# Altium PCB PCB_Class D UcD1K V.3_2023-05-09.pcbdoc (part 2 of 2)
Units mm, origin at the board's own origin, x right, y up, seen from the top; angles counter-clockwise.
Board outline 217.55 x 90.42 mm, 2 copper layers (Top Layer, Bottom Layer); 170 components, 120 nets, 574 pads, 13 vias.
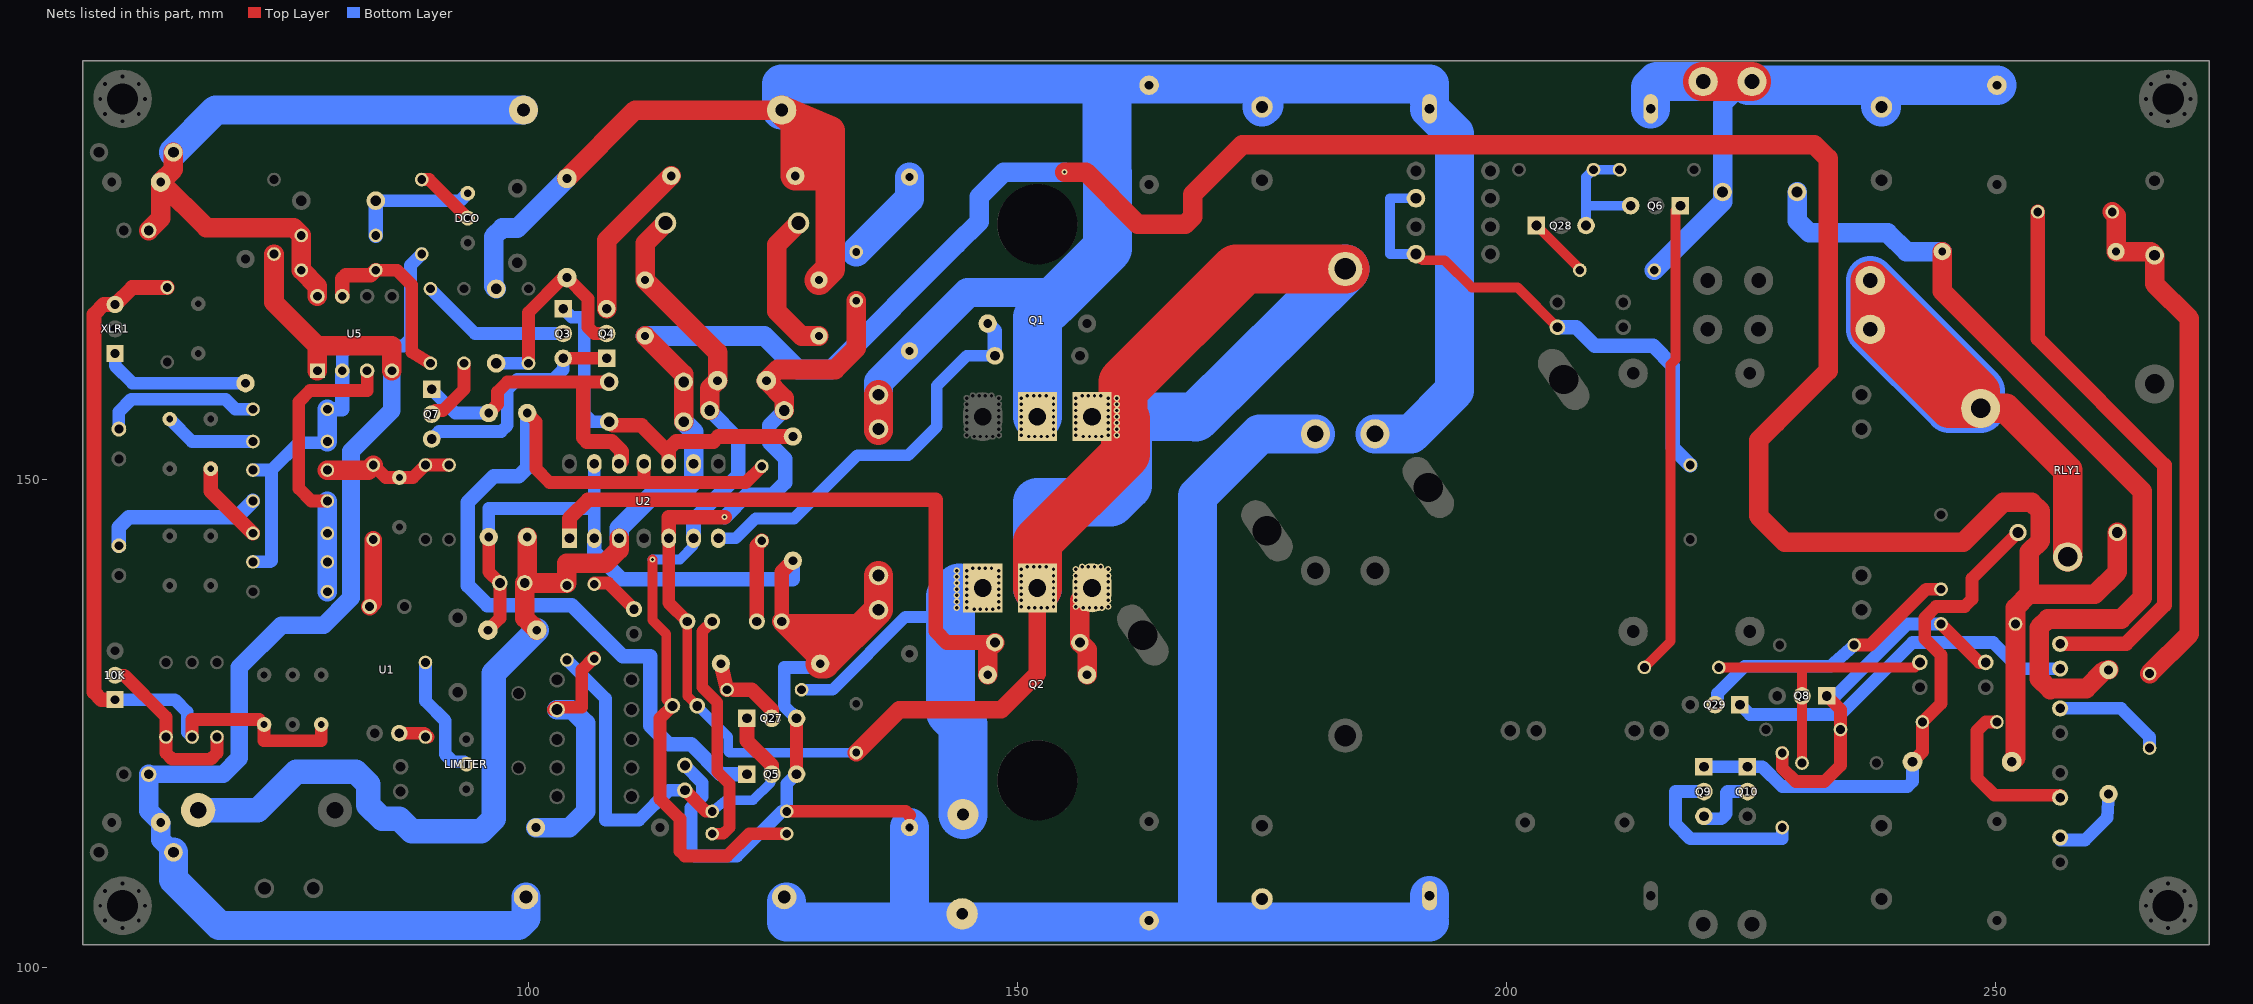
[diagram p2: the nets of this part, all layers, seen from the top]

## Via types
v1: diameter 0.61, hole 0.305, Top Layer to Bottom Layer, tented both sides, 13 vias

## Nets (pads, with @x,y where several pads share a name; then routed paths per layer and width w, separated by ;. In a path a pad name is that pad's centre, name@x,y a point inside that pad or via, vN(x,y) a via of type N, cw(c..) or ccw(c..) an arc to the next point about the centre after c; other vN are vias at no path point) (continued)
Q1_2: C1.2 C4.2 C44.1 C45.2 D8.2 D22.1 pad.2@135.763,155.111 pad.8@150.368,154.476 pad.8@150.368,155.111 pad.8@150.368,155.746 pad.8@150.368,156.381 pad.8@150.368,157.016 pad.8@150.368,157.651 pad.8@150.368,158.286 pad.8@151.003,158.54 pad.8@151.13,154.349 pad.8@151.638,158.54 pad.8@151.765,154.349 pad.8@152.4,154.349 pad.8@152.273,158.54 pad.8@152.908,158.54 pad.8@153.035,154.349 pad.8@153.67,154.476 pad.8@153.67,155.111 pad.8@153.67,155.746 pad.8@153.67,156.381 pad.8@153.67,157.016 pad.8@153.67,157.651 pad.8@153.67,158.286 Q1.2 R4.1 R7.1 R43.2 R78.1 U10.2 | length 269.2
  Top Layer w2: C4.2@103.886,180.765 110.871,187.75 R78.1@125.857,187.75 127.254,186.353 R4.1@127.254,181.019
  Top Layer w3: 128.016,185.591 128.016,181.781 R4.1@127.254,181.019 ; R7.1@129.667,170.351 130.81,171.494 130.81,181.019 ; 129.917,185.591 129.917,181.913 130.81,181.019 ; pad.2@135.763,154.984 135.763,156.716 C1.2@135.763,158.618 ; R4.1@127.254,181.019 127.254,186.353 R78.1@125.857,187.75 130.81,185.65 130.81,181.019 ; R4.1@127.254,181.019 130.81,181.019
  Bottom Layer w2: D8.2@96.647,169.462 96.393,169.716 96.393,174.796 97.282,175.685 98.806,175.685 C4.2@103.886,180.765
  Bottom Layer w3: pad.2@135.763,155.111 C1.2@135.763,158.618 135.763,159.937 R43.2@138.938,163.112 144.907,169.081 153.924,169.081
  Bottom Layer w4: R78.1@125.857,187.75 125.867,190.417 192.151,190.417 U10.2@192.151,188.512 ; C44.1@175.006,188.071 175.182,188.248 175.182,190.29 ; D22.1@186.563,154.618 190.261,154.618 194.691,159.048 194.691,185.327 U10.2@192.141,187.877
  Bottom Layer w5: Q1.2@152.019,156.381 152.019,166.541 153.924,168.319 159.191,173.586 159.131,189.782
Q2_1: D4.1 pad.8@155.956,136.95 pad.8@155.956,137.585 pad.8@155.956,138.22 pad.8@155.956,138.855 pad.8@155.956,139.49 pad.8@155.956,140.76 pad.8@155.956,140.125 pad.8@156.591,141.014 pad.8@156.718,136.823 pad.8@157.226,141.014 pad.8@157.353,136.823 pad.8@157.861,141.014 pad.8@157.988,136.823 pad.8@158.496,141.014 pad.8@158.623,136.823 pad.8@159.258,136.95 pad.8@159.258,137.585 pad.8@159.258,138.22 pad.8@159.258,138.855 pad.8@159.258,139.49 pad.8@159.258,140.76 pad.8@159.258,140.125 Q2.1 R1.2 | length 9.7
  Top Layer w2: R1.2@157.099,129.965 157.099,132.537 D4.1@156.369,133.267 156.369,137.617 Q2.1@157.607,138.855
Q2_3: pad.8@143.764,136.823 pad.8@143.764,137.458 pad.8@143.764,138.093 pad.8@143.764,138.728 pad.8@143.764,139.363 pad.8@143.764,139.998 pad.8@143.764,140.633 pad.8@144.78,136.823 pad.8@144.78,137.458 pad.8@144.78,138.093 pad.8@144.78,138.728 pad.8@144.78,139.363 pad.8@144.78,139.998 pad.8@144.78,140.633 pad.8@145.415,140.887 pad.8@145.542,136.696 pad.8@146.05,140.887 pad.8@146.177,136.696 pad.8@146.685,140.887 pad.8@146.812,136.696 pad.8@147.32,140.887 pad.8@147.447,136.696 pad.8@148.082,136.823 pad.8@148.082,137.458 pad.8@148.082,138.093 pad.8@148.082,138.728 pad.8@148.082,139.363 pad.8@148.082,139.998 pad.8@148.082,140.633 pad.9@145.542,138.855 Q2.3 R30.1 R40.1 | length 41.8
  Bottom Layer w1.2: R30.1@128.524,128.441 131.064,128.441 138.517,135.894 143.129,135.894
  Bottom Layer w5: pad.8@144.018,138.855 143.129,137.966 143.129,126.155 144.399,124.885 R40.1@144.399,115.684
Q3_2: Q3.2 R6.2 | length 15.5
  Bottom Layer w1.3: R6.2@89.916,169.462 94.488,164.89 Q3.2@103.505,164.89
Q4_2: C4.1 D8.1 Q4.2 R5.1 | length 22.1
  Top Layer w1.3: R5.1@99.949,161.842 99.949,167.049 103.505,170.605 C4.1@103.886,170.605 106.045,168.446 106.045,165.525 106.68,164.89 Q4.2@107.95,164.89
  Bottom Layer w1.3: D8.1@96.647,161.842 R5.1@99.949,161.842
Q4_3: Q4.3 R4.2 | length 16.3
  Top Layer w2: Q4.3@107.95,167.43 107.95,174.415 R4.2@114.554,181.019
Q6_1: Q6.1 R50.1 | length 48.8
  Top Layer w1: R50.1@214.122,130.727 216.789,133.394 216.789,161.715 217.297,162.223 217.297,177.463 Q6.1@217.805,177.971
Q7_2: Q7.2 R2.1 | length 7
  Top Layer w1.3: Q7.2@90.043,156.635 90.424,157.016 91.186,157.016 93.345,159.175 R2.1@93.345,161.842
Q7_3: Q3.3 Q4.1 Q7.3 | length 24.2
  Top Layer w1.3: Q3.3@103.505,162.35 Q4.1@107.95,162.35
  Bottom Layer w1.3: Q7.3@90.043,154.095 90.805,154.857 97.155,154.857 97.79,155.492 97.79,159.175 98.806,160.191 102.489,160.191 103.505,161.207 Q3.3@103.505,162.35
Q8_1: C29.1 Q8.1 R52.1 R54.2 R55.1 | length 37.4
  Top Layer w1.3: R55.1@228.219,121.964 228.219,120.44 229.616,119.043 232.537,119.043 234.188,120.694 R52.1@234.188,124.377 234.188,126.409 Q8.1@232.791,127.806 ; R54.2@244.475,135.172 248.412,131.235 C29.1@249.047,131.235
  Bottom Layer w1.3: Q8.1@232.791,127.806 233.68,127.806 241.046,135.172 R54.2@244.475,135.172
Q8_2: C26.1 Q8.2 R50.2 R51.1 | length 32
  Top Layer w1: R50.2@221.742,130.727 230.251,130.727 Q8.2@230.251,127.806 R51.1@230.251,120.948 ; 228.854,130.727 241.808,130.727 C26.1@242.316,131.235
Q9_1: D24.1 Q9.1 Q10.1 R56.1 RLY1.4 | length 55.4
  Top Layer w1.3: D24.1@241.554,121.075 242.57,122.091 R56.1@242.57,125.139 244.475,127.044 244.475,131.997 242.824,133.648 242.824,135.807 243.967,136.95 246.888,136.95 247.65,137.712 247.65,139.831 RLY1.4@252.349,144.53
  Bottom Layer w1.3: Q9.1@220.218,120.567 220.472,120.567 Q10.1@224.663,120.567 226.187,120.567 228.219,118.535 241.046,118.535 241.554,119.043 D24.1@241.554,121.075
Q9_3: Q9.3 Q10.2 | length 6.9
  Bottom Layer w1.3: Q9.3@220.218,115.233 221.996,115.233 222.504,115.741 222.504,117.9 222.631,118.027 Q10.2@224.663,118.027
Q27_1: C16.1 Q5.2 Q27.1 R31.1 R32.2 | length 45.6
  Top Layer w1.3: C16.1@115.951,118.154 118.11,115.995 R32.2@118.745,115.995
  Top Layer w1.5: Q27.1@122.301,125.52 122.301,123.869 122.301,123.234 124.841,120.694 Q5.2@124.841,119.805
  Bottom Layer w1: R32.2@118.745,115.995 120.142,117.138 122.936,117.138 124.714,118.917 Q5.2@124.714,119.551
  Bottom Layer w1.3: R31.1@103.886,131.489 107.823,127.552 107.823,115.106 111.252,115.106 114.3,118.154 C16.1@115.951,118.154
Q28_1: Q28.1 R49.2 | length 6.4
  Top Layer w1: Q28.1@203.073,175.939 207.518,171.494 R49.2@207.518,171.367
Q29_1: Q29.1 R60.2 | length 37.3
  Bottom Layer w1.3: Q29.1@223.901,126.917 224.917,125.901 234.188,125.901 241.554,133.267 249.809,133.267 252.476,130.6 R60.2@256.667,130.6
Q29_2: Q29.2 R59.2 R63.1 | length 28.5
  Top Layer w1.3: R63.1@235.585,133.013 237.236,133.013 242.951,138.728 R59.2@244.475,138.728
  Bottom Layer w1.3: Q29.2@221.361,126.917 221.615,127.171 221.615,128.06 224.409,130.854 233.172,130.854 R63.1@235.585,133.013
R6_1: R6.1 R9.2 U5.7 | length 19
  Top Layer w1.3: R9.2@84.328,171.367 86.487,171.367 88.011,169.843 88.011,162.985 R6.1@89.916,161.842
  Top Layer w1.5: U5.7@80.899,168.7 80.899,170.478 81.28,170.859 83.82,170.859 R9.2@84.328,171.367
R8_2: C39.2 C40.2 D30.1 R8.2 R11.1 U5.1 U5.4 | length 137.3
  Top Layer w2: R11.1@73.914,173.018 73.914,168.065 78.359,163.62 ; U5.4@85.979,161.08 85.979,163.62 78.359,163.62 ; 78.359,163.62 U5.1@78.359,161.08 78.359,163.62
  Bottom Layer w1.8: C39.2@61.087,119.805 68.707,119.805 70.358,121.456 70.358,130.727 74.676,135.045 78.994,135.045 81.788,137.839 81.788,152.825 85.979,157.016 U5.4@85.979,160.953
  Bottom Layer w2: C39.2@61.087,119.805 61.087,116.082 C40.2@62.317,114.852 62.317,113.114 D30.1@63.627,111.804
  Bottom Layer w3: D30.1@63.627,111.804 63.627,109.01 68.326,104.311 98.933,104.311 99.695,105.073 R8.2@99.695,107.232
R10_2: D3.1 DCO.1 R10.2 | length 13.3
  Bottom Layer w1.3: D3.1@84.328,178.479 92.964,178.479 DCO.1@93.726,179.241
  Bottom Layer w1.5: R10.2@84.328,174.923 D3.1@84.328,178.479
R12_1: R12.1 R15.2 R17.2 R19.2 R65.1 U5.2 | length 47.3
  Bottom Layer w1.3: R65.1@71.755,141.522 73.533,141.522 73.66,141.649 73.66,150.92 ; R19.2@71.755,150.92 73.66,150.92 ; R17.2@79.375,153.841 79.248,153.714 76.454,153.714 73.66,150.92 ; U5.2@80.899,161.08 80.899,162.858 81.661,163.62 87.122,163.62 87.884,164.382 87.884,171.875 R12.1@89.027,173.018
  Bottom Layer w1.5: R15.2@79.438,157.143 80.899,157.143 U5.2@80.899,161.08
  Bottom Layer w2: R17.2@79.375,153.841 R15.2@79.375,157.143
R12_2: DCO.2 R12.2 | length 6.3
  Top Layer w1.3: R12.2@89.027,180.638 89.789,180.638 DCO.2@93.726,176.701
R13_1: C37.1 R13.1 | length 16.7
  Bottom Layer w1.5: C37.1@58.039,143.173 58.039,145.078 59.055,146.094 70.104,146.094 R13.1@71.755,147.745
R13_2: R13.2 R16.2 R18.2 R65.2 U5.3 | length 31.1
  Top Layer w1.3: R13.2@79.375,147.745 77.724,147.745 76.454,149.015 76.454,157.905 77.597,159.048 83.439,159.048 U5.3@83.439,161.08
  Bottom Layer w2: R18.2@79.375,138.474 79.375,141.141 R16.2@79.375,144.443 R13.2@79.375,147.745
R15_1: C8.1 R15.1 | length 16.4
  Bottom Layer w1.3: C8.1@58.039,155.111 58.039,156.889 59.309,158.159 68.961,158.159 69.977,157.143 R15.1@71.755,157.143
R16_1: C7.2 R16.1 | length 8.4
  Top Layer w1.5: C7.2@67.437,151.047 67.437,148.761 R16.1@71.755,144.443
R17_1: C5.2 R17.1 | length 9.5
  Bottom Layer w1.3: C5.2@63.246,156.127 65.532,153.841 R17.1@71.755,153.841
R19_1: C15.1 R19.1 R28.1 R29.2 R36.2 | length 14.3
  Top Layer w1.3: R36.2@84.074,151.428 85.344,150.158 C15.1@86.995,150.158 ; C15.1@86.36,150.158 88.138,150.158 R28.1@89.408,151.428 R29.2@91.821,151.428
  Top Layer w2: R19.1@79.375,150.92 83.566,150.92 R36.2@84.074,151.428
R20_1: 10K.2 R20.1 R25.1 | length 18
  Top Layer w1.3: 10K.2@57.658,129.925 58.587,129.925 62.865,125.647 R20.1@62.865,123.615 62.865,121.964 63.5,121.329 67.437,121.329 68.072,121.964 R25.1@68.072,123.615
R21_1: 10K.1 C11.1 C12.2 R21.1 R22.2 XLR1.3 | length 78.9
  Top Layer w1.3: R22.2@65.532,123.615 65.532,125.393 72.39,125.393 C12.2@72.898,124.885 72.898,123.234 78.74,123.234 C11.1@78.74,124.885
  Top Layer w1.5: 10K.1@57.658,127.425 56.261,127.425 55.499,128.187 55.499,166.874 56.482,167.86 XLR1.3@57.658,167.858 ; XLR1.3@57.658,167.858 59.389,169.589 R21.1@62.992,169.589
  Bottom Layer w1.3: 10K.1@57.658,127.425 63.754,127.425 65.024,126.155 65.024,124.123 R22.2@65.532,123.615
R24_2: Q27.2 R24.2 R30.2 | length 8.4
  Top Layer w1.5: R24.2@119.634,131.108 R30.2@120.269,128.441 ; R30.2@120.904,128.441 122.809,128.441 124.841,126.409 Q27.2@124.841,125.52
R26_2: D12.1 R26.2 | length 15.3
  Top Layer w2: D12.1@127.577,176.193 125.349,173.965 125.349,167.176 127.889,164.636 R26.2@129.667,164.636
R36_1: R36.1 U1.2 | length 7
  Top Layer w1.8: U1.2@83.693,136.95 84.074,137.331 R36.1@84.074,143.808
R37_1: LIMITER.2 R37.1 | length 12.8
  Bottom Layer w1.3: R37.1@89.408,131.235 89.408,127.298 91.44,125.266 91.44,121.837 92.202,121.075 93.345,121.075 LIMITER.2@93.599,120.821
R37_2: R37.2 U1.3 | length 2.8
  Top Layer w1.3: U1.3@86.995,123.996 89.281,123.996 R37.2@89.662,123.615
R38_2: D17.1 R38.2 R39.2 | length 26.9
  Top Layer w1.3: D17.1@102.489,126.409 102.743,126.663 105.41,126.663 105.41,130.473 R39.2@106.68,131.743
  Bottom Layer w2: R38.2@100.711,114.344 104.14,114.344 105.791,115.995 105.791,125.012 104.394,126.409 D17.1@102.87,126.409
R39_1: R39.1 R42.1 | length 5.2
  Top Layer w1.3: R39.1@106.68,139.363 108.077,139.363 R42.1@110.744,136.696
R41_1: LED1.1 R41.1 | length 24.7
  Top Layer w1.2: R41.1@118.745,113.709 119.888,113.709 120.523,114.344 120.523,118.787 119.25,120.059 119.25,127.174 117.729,128.695 117.729,134.41 LED1.1@118.745,135.426
R43_1: C41.2 R43.1 | length 9.9
  Bottom Layer w3: C41.2@133.477,173.232 138.938,178.693 R43.1@138.938,180.892
R45_1: C20.1 D21.1 D23.2 R45.1 | length 53
  Top Layer w1: D23.2@190.754,173.018 191.389,172.383 193.675,172.383 196.469,169.589 201.168,169.589 C20.1@205.232,165.525
  Bottom Layer w1: D23.2@190.754,173.018 188.087,173.018 188.087,178.733 D21.1@190.754,178.733
  Bottom Layer w1.5: C20.1@205.232,165.525 207.137,165.525 209.042,163.62 215.011,163.62 217.043,161.588 217.043,153.206 R45.1@218.821,151.428
R47_2: Q6.3 Q28.3 R47.2 R48.1 | length 15.3
  Bottom Layer w1: R48.1@211.582,181.654 R47.2@208.915,181.654 208.154,180.893 Q28.3@208.153,175.939 208.153,177.971 Q6.3@212.725,177.971
R49_1: +100V.1 C22.2 C23.1 D26.2 R49.1 U10.1 | length 68.4
  Top Layer w4: +100V.1@220.091,190.671 +100V.1@225.092,190.669
  Bottom Layer w2: R49.1@215.138,171.367 222.123,178.352 D26.2@222.123,179.368 222.123,188.421 +100V.1@224.371,190.669
  Bottom Layer w4: U10.1@214.767,187.877 214.767,190.046 215.392,190.671 219.37,190.671 224.371,190.669 224.749,190.29 C22.2@250.19,190.29 ; 238.27,190.29 238.27,188.18 C23.1@238.379,188.071
R55_2: Q9.2 R55.2 | length 18.9
  Bottom Layer w1.3: Q9.2@220.218,118.027 217.297,118.027 217.297,114.725 218.821,113.201 228.219,113.201 R55.2@228.219,114.344
R56_2: R56.2 R57.1 | length 16.5
  Top Layer w1.3: R56.2@250.19,125.139 249.047,125.139 248.158,124.25 248.158,119.424 249.936,117.646 R57.1@256.667,117.646
R58_1: R58.1 R62.2 | length 11.5
  Bottom Layer w1.3: R58.1@256.667,126.536 262.89,126.536 265.811,123.615 R62.2@265.811,122.472
R60_1: R60.1 R61.2 | length 57.9
  Top Layer w1.5: R61.2@254.381,177.336 254.381,164.382 267.335,151.428 267.335,137.077 263.398,133.14 R60.1@256.667,133.14
R61_1: D25.2 R61.1 R62.1 R81.1 | length 54.3
  Top Layer w2: R61.1@262.001,177.336 262.382,176.955 R81.1@262.382,173.272 265.938,173.272 D25.2@266.319,172.891 266.319,169.97 269.875,166.414 269.875,134.156 R62.1@265.811,130.092
R78_2: C43.1 C46.2 D31.2 R9.1 R10.1 R78.2 U5.8 | length 70.2
  Top Layer w2: C43.1@61.087,175.431 62.317,176.661 C46.2@62.317,180.384 63.627,181.694 D31.2@63.627,183.432 ; C46.2@62.317,180.384 66.983,175.718 75.914,175.718 R10.1@76.708,174.923 R9.1@76.708,171.367 78.359,169.716 U5.8@78.359,168.7
  Bottom Layer w3: D31.2@63.627,183.432 67.945,187.75 R78.2@99.441,187.75
R81_2: D26.1 R64.1 R81.2 | length 88.4
  Top Layer w2: R81.2@244.602,173.272 244.602,169.208 265.049,148.761 265.049,137.837 262.893,135.68 255.397,135.68 254.508,134.791 254.508,129.584 255.651,128.441 255.778,128.568 259.334,128.568 261.112,130.346 R64.1@261.62,130.473
  Bottom Layer w2: D26.1@229.743,179.368 229.743,176.447 231.013,175.177 239.014,175.177 240.919,173.272 R81.2@244.602,173.272
R126_1: R33.1 R126.1 | length 8.5
  Top Layer w1.5: R126.1@123.317,135.426 123.317,143.173 R33.1@123.825,143.681
RLY1_5: P2.1 RLY1.5 | length 124.5
  Top Layer w3: RLY1.5@248.529,157.23 251.12,157.23 257.429,150.92 RLY1.5@257.429,142.03
  Top Layer w4: P2.1@237.236,170.311 P2.1@237.233,165.309 245.312,157.23 RLY1.5@248.529,157.23 248.529,159.018 P2.1@237.236,170.311
  Bottom Layer w5: P2.1@237.236,170.311 P2.1@237.233,165.309 ; P2.1@237.236,170.311 248.529,159.018 RLY1.5@248.529,157.23 ; P2.1@237.233,165.309 240.45,165.309 ; P2.1@237.233,165.309 245.312,157.23 RLY1.5@248.529,157.23 ; P2.1@237.233,165.309 240.45,165.309 ; 240.45,165.309 RLY1.5@248.529,157.23 ; 240.45,165.309 RLY1.5@248.529,157.23
S$24602: 
S$24604: 
S$24606: 
S$24608: 
S$24610: 
S$24612: 
S$24620: 
S$24635: 
S$24640: 
S$24642: 
S$24644: 
S$24646: 
S$24648: 
S$24650: 
S$24652: 
S$24654: 
S$24656: 
S$24658: 
S$24677: 
S$24679: 
S$24683: 
S$24687: 
S$24689: 
S$24691: 
S$24693: 
S$24695: 
S$24697: 
S$24703: 
S$24844: 
S$24846: 
S$24886: 
S$24934: 
S$30470: 
S$32420: 
S$32422: 
U2_1: D4.2 R1.1 U2.1 | length 63.9
  Top Layer w1.5: U2.1@104.14,143.935 104.14,145.967 106.045,147.872 114.173,147.872 129.667,147.872 141.605,147.872 141.605,134.41 142.748,133.267 D4.2@147.669,133.267
  Top Layer w2: R1.1@146.939,129.965 146.939,132.537 D4.2@147.669,133.267
U2_2: C1.1 C2.1 C3.2 C16.2 C17.2 C18.1 D1.2 pad.1@135.763,140.125 Q5.3 Q27.3 R3.2 R8.1 R24.1 R32.1 R40.2 R44.1 R46.2 R126.2 U2.2 U2.13 U3.2 | length 297.4
  Top Layer w1.3: C18.1@95.798,134.537 97.028,135.767 C17.2@97.028,139.363 95.885,140.506 R46.2@95.885,144.062 ; R32.1@126.365,115.995 138.557,115.995 138.938,115.614 ; Q5.3@127.381,119.805 Q27.3@127.381,125.52
  Top Layer w1.5: R3.2@127,141.649 125.857,140.506 R126.2@125.857,135.426 ; R24.1@129.794,131.108 129.794,131.489 R126.2@125.857,135.426 ; C1.1@135.763,136.618 134.572,135.426 R126.2@125.857,135.426
  Top Layer w2: 129.55,134.156 129.55,131.352 R24.1@129.794,131.108 129.794,131.489 R126.2@125.857,135.426 127.127,134.156 131.064,134.156
  Top Layer w3: R24.1@129.794,131.108 130.254,131.108 135.763,136.618 135.763,138.326 pad.1@135.763,140.125
  Bottom Layer w1.3: R46.2@95.885,144.062 95.885,146.983 106.299,146.983 106.68,146.602 ; U2.2@106.68,143.935 106.68,146.602 ; U2.13@106.68,151.555 106.68,146.602 ; C16.2@115.951,120.694 117.729,118.916 117.729,117.519 116.586,116.376 116.586,111.804 116.967,111.423 121.285,111.423 125.857,115.995 R32.1@126.365,115.995 126.365,118.789 Q5.3@127.381,119.805 ; Q27.3@127.381,125.52 126.111,126.79 126.111,130.727 129.413,130.727 R24.1@129.794,131.108
  Bottom Layer w1.5: U2.2@106.68,143.935 106.68,142.538 109.474,139.744 127,139.744 R3.2@127,141.649
  Bottom Layer w4: 126.365,104.819 R8.1@126.365,106.724 ; 126.375,104.692 192.151,104.692 ; 138.938,105.515 R44.1@138.938,114.344 ; 168.394,104.692 168.394,148.246 174.767,154.619 D1.2@180.467,154.618 ; 192.141,105.327 U3.2@192.141,107.359
U2_3: C17.1 C18.2 D2.2 D6.1 D19.2 D24.2 R26.1 R31.2 R35.2 R54.1 RLY1.3 U2.3 U2.9 | length 363.1
  Top Layer w2: R35.2@99.822,144.062 99.822,139.617 C17.1@99.568,139.363 ; C18.2@100.798,134.537 99.568,135.767 C17.1@99.568,139.363 ; U2.3@109.22,143.935 109.22,142.792 107.823,141.395 103.886,141.395 103.886,139.363 C17.1@99.568,139.363 ; R26.1@111.887,164.636 115.824,160.699 D19.2@115.824,159.937 D2.2@115.824,155.873 ; v1(154.813,181.4) 156.972,181.4 162.306,176.066 167.132,176.066 167.894,176.828 167.894,179.114 172.974,184.194 231.521,184.194 232.918,182.797 232.918,161.08 225.806,153.968 ; 227.617,155.779 225.806,153.968 ; D24.2@251.714,121.075 252.095,121.456 R54.1@252.095,135.172 252.095,136.823 253.492,138.22 ; RLY1.3@262.509,144.53 262.509,140.506 260.223,138.22 253.492,138.22 ; 225.806,153.968 225.806,146.221 228.473,143.554 246.761,143.554 250.825,147.618 253.746,147.618 254.635,146.729 254.635,143.681 253.492,142.538 253.492,138.22
  Bottom Layer w2: U2.3@109.22,143.935 109.22,144.951 113.538,149.269 116.332,149.269 116.84,149.777 U2.9@116.84,151.555 116.84,154.857 D2.2@115.824,155.873 ; R26.1@111.887,164.636 124.079,164.636 127.508,161.207 130.937,161.207 143.764,174.034 146.05,176.32 146.05,178.86 148.59,181.4 v1(154.813,181.4)
  Bottom Layer w2.5: D6.1@66.152,116.122 72.263,116.122 76.2,120.059 82.169,120.059 82.296,120.059 83.566,118.789 83.566,116.63 84.963,115.233 86.741,115.233 88.011,113.963 95.123,113.963 96.393,115.233 96.393,119.805 96.393,130.133 C18.2@100.798,134.537
U2_5: 30UH.1 C24.2 C25.1 C41.1 C42.2 D11.1 LED1.2 pad.8@150.368,136.95 pad.8@150.368,137.585 pad.8@150.368,138.22 pad.8@150.368,138.855 pad.8@150.368,139.49 pad.8@150.368,140.76 pad.8@150.368,140.125 pad.8@151.003,141.014 pad.8@151.13,136.823 pad.8@151.638,141.014 pad.8@151.765,136.823 pad.8@152.4,136.823 pad.8@152.273,141.014 pad.8@152.908,141.014 pad.8@153.035,136.823 pad.8@153.67,136.95 pad.8@153.67,137.585 pad.8@153.67,138.22 pad.8@153.67,138.855 pad.8@153.67,139.49 pad.8@153.67,140.76 pad.8@153.67,140.125 pad.8@155.956,154.476 pad.8@155.956,155.111 pad.8@155.956,155.746 pad.8@155.956,156.381 pad.8@155.956,157.016 pad.8@155.956,157.651 pad.8@155.956,158.286 pad.8@156.591,158.54 pad.8@156.718,154.349 pad.8@157.226,158.54 pad.8@157.353,154.349 pad.8@157.861,158.54 pad.8@157.988,154.349 pad.8@158.496,158.54 pad.8@158.623,154.349 pad.8@159.258,154.476 pad.8@159.258,155.111 pad.8@159.258,155.746 pad.8@159.258,156.381 pad.8@159.258,157.016 pad.8@159.258,157.651 pad.8@159.258,158.286 pad.8@160.147,154.476 pad.8@160.147,155.111 pad.8@160.147,155.746 pad.8@160.147,156.381 pad.8@160.147,157.016 pad.8@160.147,157.651 pad.8@160.147,158.286 pad.9@158.75,156.381 pad.9@158.623,156.381 Q1.3 Q2.2 U2.5 | length 249.2
  Top Layer w1: LED1.2@116.205,135.426 116.205,127.806 C24.2@117.221,126.79
  Top Layer w1.3: U2.5@114.3,143.935 114.3,137.331 LED1.2@116.205,135.426
  Top Layer w1.5: U2.5@114.3,143.935 114.3,146.094 v1(120.015,146.094)
  Top Layer w1.8: C42.2@133.477,122.004 137.882,126.409 148.336,126.409 152.019,130.092 Q2.2@152.019,138.855
  Top Layer w2: D11.1@126.111,157.016 126.111,158.246 C25.1@124.293,160.064 125.436,161.207 131.318,161.207 133.477,163.366 C41.1@133.477,168.232
  Top Layer w3: 161.036,156.127 161.036,157.905 174.625,171.494 30UH.1@183.515,171.494
  Top Layer w5: Q2.2@152.019,138.855 152.019,143.554 161.036,152.571 161.036,156.127 160.782,156.381 ; 160.782,156.635 160.782,159.937 172.339,171.494 30UH.1@183.515,171.494
  Bottom Layer w1: C24.2@117.221,126.79 120.396,123.615 120.396,122.091 120.483,122.004 C42.2@133.477,122.004
  Bottom Layer w1.5: v1(120.015,146.094) 122.301,148.38 124.968,148.38 126.238,149.65 126.238,152.063 124.587,153.714 124.587,155.492 D11.1@126.111,157.016
  Bottom Layer w5: Q2.2@152.019,138.855 152.019,147.618 159.509,147.618 161.226,149.333 161.232,156.381 ; pad.8@159.962,156.381 163.195,156.381 168.212,156.353 30UH.1@183.515,171.494
U2_6: C24.1 C25.2 D11.2 D12.2 R7.2 R41.2 U2.6 | length 89.3
  Top Layer w1: v1(112.649,141.776) 112.649,135.553 114.046,134.156 114.046,127.425 C24.1@114.681,126.79
  Top Layer w1.3: C24.1@114.681,126.79 113.411,125.52 113.411,117.265 115.443,115.233 115.443,111.931 115.951,111.423 120.269,111.423 122.555,113.709 R41.2@126.365,113.709
  Top Layer w2: D12.2@113.977,176.193 111.887,174.103 R7.2@111.887,170.351 119.293,162.945 C25.2@119.293,160.064 118.491,159.262 D11.2@118.491,157.016
  Bottom Layer w1: v1(112.649,141.776) 115.443,141.776 116.84,143.173 U2.6@116.84,143.935
  Bottom Layer w1.5: U2.6@116.84,143.935 116.84,145.84 121.412,150.412 121.412,154.095 D11.2@118.491,157.016
U2_7: D15.1 R34.1 U2.7 | length 42.1
  Bottom Layer w1.2: U2.7@119.38,143.935 121.158,143.935 123.19,145.967 127.127,145.967 133.604,152.444 138.811,152.444 141.732,155.365 141.732,159.556 144.78,162.604 D15.1@147.669,162.604
  Bottom Layer w1.5: R34.1@146.939,165.906 147.669,165.176 D15.1@147.669,162.604
U2_10: D2.1 Q3.1 R3.1 U2.10 | length 38.4
  Top Layer w1.5: D2.1@108.204,155.873 108.585,155.492 111.506,155.492 114.3,152.698 U2.10@114.3,151.555 114.3,153.079 115.062,153.841 118.872,153.841 119.38,154.349 R3.1@127,154.349
  Bottom Layer w1.3: Q3.1@103.505,167.43 104.394,166.541 105.283,166.541 105.664,166.16 105.664,156.635 106.426,155.873 D2.1@108.204,155.873
U2_11: Q5.1 R33.2 R35.1 U2.11 | length 95.3
  Top Layer w1.3: R35.1@99.822,156.762 100.711,155.873 100.711,151.047 102.108,149.65 112.395,149.65 ; U2.11@111.76,151.555 111.76,149.65 122.174,149.65 R33.2@123.825,151.301
  Bottom Layer w1.5: R35.1@99.822,156.762 99.822,151.174 98.933,150.285 96.393,150.285 93.726,147.618 93.726,139.109 95.758,137.077 104.394,137.077 109.601,131.87 112.395,131.87 112.395,124.758 114.3,122.853 116.594,122.853 119.642,119.805 Q5.1@122.174,119.805
U2_12: D19.1 Q7.1 R46.1 U2.12 | length 32.7
  Top Layer w1.3: R46.1@95.885,156.762 96.774,157.651 96.774,158.921 97.79,159.937 D19.1@108.204,159.937
  Top Layer w1.5: 105.537,159.81 105.537,154.222 105.918,153.841 108.458,153.841 109.474,152.825 109.474,151.809 U2.12@109.22,151.555
  Bottom Layer w1.3: Q7.1@90.043,159.175 92.456,156.762 R46.1@95.885,156.762
XLR1_1: R27.1 XLR1.1 | length 15.3
  Bottom Layer w1.3: XLR1.1@57.658,162.858 57.658,161.588 59.436,159.81 R27.1@70.993,159.81
YG1_2: R64.2 YG1.2 | length 8.2
  Bottom Layer w1.3: YG1.2@256.667,113.074 259.207,113.074 261.493,115.36 R64.2@261.62,117.773
pads on no net: Q1. Q2. U2.4 U2.8 U2.14 U5.5 U5.6

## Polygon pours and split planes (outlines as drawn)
GND on Bottom Layer "Bottom Layer-GND" (solid, pour order 0): 55.118,192.278 269.941,192.278 271.61,102.743 269.941,102.743 55.118,102.743
GND on Top Layer "Top Layer-GND" (solid, pour order 2): 54.864,192.405 63.1,192.405 271.61,192.405 271.61,102.9 54.864,102.9

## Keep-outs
Keep-Out Layer:
  lines w0.254: 54.61,105.576 ccw(c57.61,105.576) 57.61,102.576 ; 54.61,189.576 cw(c57.61,189.576) 57.61,192.576 ; 268.61,102.576 ccw(c268.61,105.576) 271.61,105.576 ; 268.61,192.576 cw(c268.61,189.576) 271.61,189.576

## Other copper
Top Layer:
  region net Q2_3: 144.018,141.395 147.701,141.395 147.701,136.442 147.701,136.315 143.383,136.315 143.383,141.395
  region net U2_5: 160.274,153.841 156.591,153.841 156.591,158.794 156.591,158.921 160.909,158.921 160.909,153.841
Bottom Layer:
  region net Q2_3: 144.018,141.395 147.701,141.395 147.701,136.442 147.701,136.315 143.383,136.315 143.383,141.395
  region net U2_5: 160.147,153.841 156.464,153.841 156.464,158.794 156.464,158.921 160.782,158.921 160.782,153.841

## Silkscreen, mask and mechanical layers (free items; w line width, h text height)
Top Overlay:
  lines w0.254: 54.483,102.489 54.483,192.659 271.78,192.659 271.78,102.489 54.483,102.489
  text "UcD1k V3" at 142.748,144.971 h2.5
  text "BIAS" at 81.28,110.315 h1.2
  text "+" at 82.379,105.157 h2.03 r135
  text "-" at 68.58,103.803 h2.03 r90
Top Paste:
  region: 144.018,141.395 147.701,141.395 147.701,136.442 147.701,136.315 143.383,136.315 143.383,141.395
  region: 160.274,153.841 156.591,153.841 156.591,158.794 156.591,158.921 160.909,158.921 160.909,153.841
Bottom Paste:
  region: 144.018,141.395 147.701,141.395 147.701,136.442 147.701,136.315 143.383,136.315 143.383,141.395
  region: 160.147,153.841 156.464,153.841 156.464,158.794 156.464,158.921 160.782,158.921 160.782,153.841
Top Solder:
  region: 144.018,141.395 147.701,141.395 147.701,136.442 147.701,136.315 143.383,136.315 143.383,141.395
  region: 160.274,153.841 156.591,153.841 156.591,158.794 156.591,158.921 160.909,158.921 160.909,153.841
Bottom Solder:
  region: 144.018,141.395 147.701,141.395 147.701,136.442 147.701,136.315 143.383,136.315 143.383,141.395
  region: 160.147,153.841 156.464,153.841 156.464,158.794 156.464,158.921 160.782,158.921 160.782,153.841
  lines w1: 175.006,107.105 175.034,107.077 175.034,104.438 ; 238.379,107.232 238.501,107.11 238.501,104.819
  lines w1.4: 183.896,133.013 185.039,133.013
  lines w2: 158.75,155.365 159.097,155.018 161.369,155.018 ; 168.379,104.438 168.275,104.542 168.275,147.999 174.879,154.603 180.467,154.603 ; 180.34,140.633 180.467,140.76 186.563,140.76 ; 183.261,134.075 191.978,134.075 192.405,133.648 ; 184.785,139.744 184.531,139.744 181.864,139.744 181.61,139.49 181.61,127.679 183.261,126.028 183.261,138.22 180.975,140.506 180.594,140.506 180.594,126.79 183.769,123.615 183.896,123.615 ; 185.418,134.075 187.851,136.509 187.851,138.202 ; 185.423,139.621 186.433,139.621 ; 185.81,125.529 185.81,132.293 187.592,134.075 ; 186.436,154.603 190.119,154.603 194.691,159.175 194.691,185.21 192.151,187.75 ; 187.498,134.075 187.498,127.217 183.896,123.615 ; 187.875,138.178 188.711,137.342 188.711,134.075 ; 190.598,136.725 213.897,136.725 214.011,136.839 ; 214.757,107.486 216.281,107.486 219.329,104.438 249.936,104.438 250.317,104.819 ; 214.757,187.75 214.757,190.544 215.138,190.544 250.19,190.544 250.19,190.29 ; 220.599,167.609 220.853,167.863 225.933,167.863 ; 223.164,165.271 223.164,169.996 223.393,170.224 ; 238.379,188.131 238.428,188.181 238.428,190.29 ; 256.459,151.174 265.095,159.81 266.446,159.81 ; 183.896,123.615 183.896,138.093 186.563,140.76 ; 186.433,139.621 192.405,133.648 ; 186.433,139.621 184.901,138.089 184.901,134.075 186.433,135.607 186.433,139.621 ; 186.563,140.76 192.532,134.791 212.979,134.791 211.836,133.648 192.405,133.648 ; 220.599,165.271 225.806,165.271 225.933,165.398 225.933,170.224 220.599,170.224 220.599,165.271
  lines w2.5: 125.857,187.623 125.857,190.417 192.151,190.417 192.151,187.75 ; 126.111,107.359 126.365,107.105 126.365,104.565 126.492,104.438 192.151,104.438 192.151,107.359 ; 144.526,115.868 144.526,125.139 143.129,126.536 143.129,138.601 143.256,138.728 146.558,138.728 ; 152.019,138.855 152.019,147.618 152.146,147.745 159.385,147.745 161.369,149.729 161.369,156.381 ; 152.019,156.127 152.019,166.287 159.214,173.482 159.214,190.417 ; 157.861,156.381 168.529,156.381 183.642,171.494 ; 187.594,139.729 187.948,140.082 217.254,140.082 ; 189.241,138.083 215.254,138.083 215.655,138.483
  lines w3: 212.979,134.791 212.979,135.807 228.346,151.174 257.81,151.174 266.446,159.81
  lines w4: 248.539,157.27 240.411,165.398 ; 240.411,165.398 237.236,168.573 237.236,170.351 237.236,165.398 240.411,165.398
